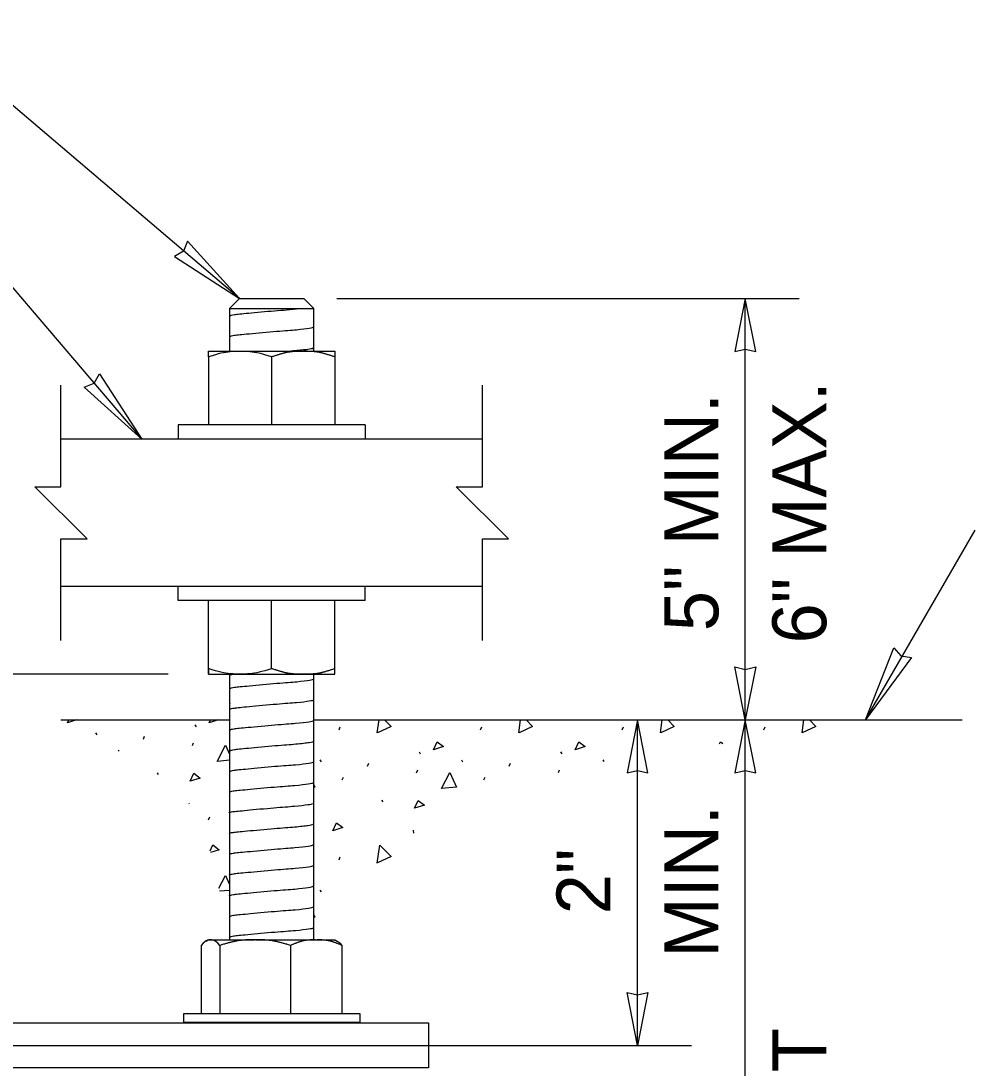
# Model space of a CAD drawing. Extents: x 99862 to 103680, y 99594 to 102199.
# Drawn here: x 101383.8 to 101666.8, y 100917.9 to 101228.5 of the extents above; entities that cross this region are included whole.
import ezdxf

# ---------------------------------------------------------------- set-up
doc = ezdxf.new("R2010")
doc.units = 0
for name, color, linetype in [('Level 15', 7, 'Continuous'), ('Level 19', 7, 'Continuous'), ('Level 2', 7, 'Continuous'), ('Level 20', 7, 'Continuous'), ('Level 9', 7, 'Continuous')]:
    doc.layers.add(name, color=color, linetype=linetype)

msp = doc.modelspace()

# ---------------------------------------------------------------- linework, layer by layer
at = {"layer": 'Level 15'}
for p, q in [((101448.66, 101146.14), (101351.93, 101228.51)), ((101370.94, 101161.59), (101419.68, 101104.48)), ((101477.49, 101146.14), (101515.57, 101146.14)), ((101515.57, 101146.14), (101614.68, 101146.14)), ((101598.68, 101021.14), (101598.68, 101146.14)), ((101634.32, 101021.14), (101666.82, 101077.43)), ((101427.43, 101034.69), (101297.26, 101034.69)), ((101435.38, 101019.67), (101435.75, 101019.11)), ((101478.16, 101018.26), (101478.54, 101019.1)), ((101520.16, 101018.26), (101520.54, 101019.1)), ((101562.16, 101018.26), (101562.54, 101019.1)), ((101566.68, 100924.6), (101566.68, 101021.14)), ((101598.68, 100723.67), (101598.68, 101021.14)), ((101604.16, 101018.26), (101604.54, 101019.1)), ((101405.93, 101017.29), (101406.31, 101016.74)), ((101420.12, 101015.47), (101420.5, 101016.31)), ((101434.67, 101013.52), (101435.04, 101014.36)), ((101412.77, 101011.84), (101412.94, 101012.22)), ((101472.46, 101009.27), (101472.83, 101008.71)), ((101501.9, 101011.65), (101502.27, 101011.09)), ((101514.46, 101009.27), (101514.83, 101008.71)), ((101543.9, 101011.65), (101544.27, 101011.09)), ((101556.46, 101009.27), (101556.75, 101008.84)), ((101486.64, 101007.45), (101487.02, 101008.29)), ((101501.19, 101005.5), (101501.57, 101006.34)), ((101528.64, 101007.45), (101529.02, 101008.29)), ((101543.23, 101005.6), (101543.57, 101006.34)), ((101424.23, 101005.41), (101424.53, 101004.96)), ((101479.09, 101003.36), (101479.47, 101004.2)), ((101521.09, 101003.36), (101521.47, 101004.2)), ((101490.75, 100997.39), (101491.12, 100996.83)), ((101433.65, 100996.47), (101433.67, 100996.29)), ((101439.47, 100991.52), (101439.84, 100992.36)), ((101500.17, 100988.45), (101500.27, 100987.61)), ((101478.16, 100979.67), (101478.54, 100980.51)), ((101472.46, 100970.68), (101472.83, 100970.13)), ((101318.38, 100924.6), (101582.68, 100924.6))]:
    msp.add_line(p, q, dxfattribs=at)
for points in [[(101448.66, 101146.14), (101433.18, 101163.18), (101432.06, 101160.22), (101429.32, 101158.63)], [(101598.68, 101146.14), (101595.6, 101130.41), (101598.68, 101131.14), (101601.77, 101130.41)], [(101419.68, 101104.48), (101402.59, 101119.91), (101405.55, 101121.04), (101407.13, 101123.78)], [(101634.32, 101021.14), (101642.75, 101042.56), (101644.85, 101040.19), (101647.98, 101039.68)], [(101598.68, 101021.14), (101595.6, 101036.86), (101598.68, 101036.14), (101601.77, 101036.86)], [(101566.68, 101021.14), (101563.6, 101005.41), (101566.68, 101006.14), (101569.77, 101005.41)], [(101598.68, 101021.14), (101595.6, 101005.41), (101598.68, 101006.14), (101601.77, 101005.41)], [(101566.68, 100924.6), (101563.6, 100940.33), (101566.68, 100939.6), (101569.77, 100940.33)]]:
    msp.add_lwpolyline(points, close=True, dxfattribs=at)
for points in [[(101395.68, 101044.73), (101395.68, 101074.86), (101403.43, 101074.86), (101387.94, 101090.35), (101395.68, 101090.35), (101395.68, 101120.48)], [(101520.68, 101044.73), (101520.68, 101074.86), (101528.43, 101074.86), (101512.94, 101090.35), (101520.68, 101090.35), (101520.68, 101120.48)], [(101397.65, 101020.32), (101398.05, 101021.14)], [(101400.28, 101021.14), (101397.65, 101020.32)], [(101439.65, 101020.32), (101440.05, 101021.14)], [(101442.28, 101021.14), (101439.65, 101020.32)], [(101489.5, 101017.3), (101490.04, 101021.14)], [(101491.69, 101021.14), (101493.58, 101019.18), (101489.59, 101017.33)], [(101531.5, 101017.3), (101532.04, 101021.14)], [(101533.69, 101021.14), (101535.58, 101019.18), (101531.59, 101017.33)], [(101573.5, 101017.3), (101574.04, 101021.14)], [(101575.69, 101021.14), (101577.58, 101019.18), (101573.59, 101017.33)], [(101615.5, 101017.3), (101616.04, 101021.14)], [(101617.69, 101021.14), (101619.58, 101019.18), (101615.59, 101017.33)], [(101441.98, 101008.86), (101444.5, 101013.62), (101445.68, 101010.97)], [(101506.17, 101012.3), (101507.29, 101014.63), (101509.16, 101013.23), (101506.17, 101012.3)], [(101548.17, 101012.3), (101549.29, 101014.63), (101551.16, 101013.23), (101548.17, 101012.3)], [(101591, 101014.02), (101591.29, 101014.63), (101591.96, 101014.13)], [(101445.68, 101009.17), (101442.08, 101008.86)], [(101434.02, 101002.99), (101435.13, 101005.32), (101437, 101003.92), (101434.02, 101002.99)], [(101508.51, 101000.84), (101511.02, 101005.59), (101512.98, 101001.21), (101508.6, 101000.84)], [(101470.68, 101001.88), (101470.98, 101001.21), (101470.68, 101001.19)], [(101500.54, 100994.97), (101501.66, 100997.3), (101503.52, 100995.9), (101500.54, 100994.97)], [(101476.32, 100988.3), (101477.43, 100990.63), (101479.3, 100989.23), (101476.32, 100988.3)], [(101439.92, 100982.29), (101440.77, 100984.06), (101442.64, 100982.66), (101440.03, 100981.85)], [(101489.5, 100978.71), (101490.24, 100984.04), (101493.58, 100980.59), (101489.59, 100978.74)], [(101442.48, 100971.21), (101444.5, 100975.03), (101445.68, 100972.38)], [(101445.68, 100970.58), (101442.67, 100970.32)], [(101470.68, 100963.29), (101470.98, 100962.63), (101470.68, 100962.6)]]:
    msp.add_lwpolyline(points, dxfattribs=at)
at = {"layer": 'Level 19'}
msp.add_lwpolyline([(101318.38, 100931.28), (101504.66, 100931.28), (101504.66, 100917.92), (101318.38, 100917.92)], dxfattribs=at)
at = {"layer": 'Level 2'}
for p, q in [((101395.68, 101021.14), (101445.68, 101021.14)), ((101470.68, 101021.14), (101662.99, 101021.14))]:
    msp.add_line(p, q, dxfattribs=at)
at = {"layer": 'Level 9'}
for p, q in [((101448.66, 101146.14), (101445.68, 101143.16)), ((101448.66, 101146.14), (101467.71, 101146.14)), ((101470.68, 101143.16), (101467.71, 101146.14)), ((101445.68, 101143.16), (101470.68, 101143.16)), ((101445.68, 101143.16), (101445.68, 101130.52)), ((101470.68, 101130.52), (101470.68, 101143.16)), ((101439.43, 101130.52), (101467.77, 101130.52)), ((101467.77, 101130.52), (101476.93, 101130.52)), ((101439.43, 101128.85), (101439.43, 101108.65)), ((101458.18, 101128.85), (101458.18, 101108.65)), ((101476.93, 101128.85), (101476.93, 101108.65)), ((101485.96, 101108.65), (101430.41, 101108.65)), ((101430.41, 101108.65), (101430.41, 101104.48)), ((101458.18, 101108.65), (101439.43, 101108.65)), ((101476.93, 101108.65), (101458.18, 101108.65)), ((101485.96, 101108.65), (101485.96, 101104.48)), ((101520.68, 101104.48), (101395.68, 101104.48)), ((101520.68, 101060.73), (101395.68, 101060.73)), ((101430.41, 101056.57), (101430.41, 101060.73)), ((101485.96, 101056.57), (101485.96, 101060.73)), ((101485.96, 101056.57), (101430.41, 101056.57)), ((101458.18, 101056.57), (101439.43, 101056.57)), ((101439.43, 101036.37), (101439.43, 101056.57)), ((101476.93, 101056.57), (101458.18, 101056.57)), ((101458.18, 101036.36), (101458.18, 101056.57)), ((101476.93, 101036.36), (101476.93, 101056.57)), ((101439.43, 101034.69), (101467.34, 101034.69)), ((101445.68, 101034.69), (101445.68, 100955.94)), ((101448.47, 101034.69), (101449.15, 101034.69)), ((101467.11, 101034.69), (101468, 101034.69)), ((101467.77, 101034.69), (101467.34, 101034.69)), ((101467.77, 101034.69), (101467.34, 101034.69)), ((101467.77, 101034.69), (101476.93, 101034.69)), ((101470.68, 100955.94), (101470.68, 101034.69)), ((101437.22, 100954.27), (101437.22, 100934.07)), ((101438.72, 100955.56), (101439.39, 100955.94)), ((101439.39, 100955.94), (101453.05, 100955.94)), ((101442.83, 100954.27), (101442.83, 100934.07)), ((101453.52, 100955.94), (101453.05, 100955.94)), ((101453.52, 100955.94), (101453.05, 100955.94)), ((101453.52, 100955.94), (101471.72, 100955.94)), ((101462.61, 100955.94), (101463.37, 100955.94)), ((101463.74, 100954.27), (101463.74, 100934.07)), ((101471.72, 100955.94), (101476.89, 100955.94)), ((101476.11, 100955.94), (101476.37, 100955.94)), ((101476.89, 100955.94), (101477.55, 100955.56)), ((101479.04, 100954.27), (101479.04, 100934.07))]:
    msp.add_line(p, q, dxfattribs=at)
msp.add_lwpolyline([(101484.33, 100931.37), (101432.13, 100931.37), (101432.13, 100934.07), (101484.33, 100934.07)], close=True, dxfattribs=at)
for points, degree in [([(101445.67, 101140.97), (101445.71, 101141), (101445.76, 101141.04), (101446.62, 101141.42), (101450.62, 101141.77), (101459.36, 101142.6), (101463.79, 101142.9), (101466.51, 101143.16)], 3), ([(101445.67, 101134.83), (101445.71, 101134.86), (101445.76, 101134.9), (101446.62, 101135.28), (101450.62, 101135.63), (101460.33, 101136.55), (101465.84, 101136.9), (101469.8, 101137.41), (101470.55, 101137.57), (101470.67, 101137.76)], 3), ([(101439.43, 101128.85), (101439.43, 101129.87), (101439.43, 101130.52), (101439.43, 101130.52)], 2), ([(101458.18, 101128.85), (101455.12, 101129.87), (101452.01, 101130.52), (101445.64, 101130.52), (101442.5, 101129.87), (101439.43, 101128.85)], 3), ([(101467.34, 101130.52), (101464.23, 101130.5), (101461.17, 101129.85), (101458.18, 101128.85)], 2), ([(101462.26, 101130.52), (101464.75, 101130.72), (101466.98, 101130.91), (101469.72, 101131.26), (101470.44, 101131.41), (101470.67, 101131.63)], 3), ([(101476.93, 101128.85), (101473.93, 101129.85), (101470.89, 101130.5), (101467.77, 101130.52)], 2), ([(101476.93, 101130.52), (101476.93, 101130.47), (101476.93, 101129.82), (101476.93, 101128.85)], 2), ([(101439.43, 101034.69), (101439.43, 101034.69), (101439.43, 101035.35), (101439.43, 101036.37)], 2), ([(101458.18, 101036.36), (101455.12, 101035.34), (101452.01, 101034.69), (101445.64, 101034.69), (101442.5, 101035.34), (101439.43, 101036.37)], 3), ([(101439.43, 101036.36), (101439.43, 101035.35), (101439.43, 101034.69), (101439.43, 101034.69)], 2), ([(101439.43, 101034.69), (101439.43, 101034.69), (101439.43, 101034.69), (101439.43, 101034.69)], 2), ([(101447.36, 101034.69), (101446.71, 101034.63), (101446.27, 101034.57), (101446.01, 101034.51), (101445.8, 101034.47), (101445.71, 101034.42), (101445.75, 101034.37)], 4), ([(101445.75, 101034.42), (101445.74, 101034.4), (101445.74, 101034.39), (101445.75, 101034.37)], 3), ([(101467.34, 101034.69), (101464.23, 101034.72), (101461.17, 101035.37), (101458.18, 101036.36)], 2), ([(101476.93, 101036.36), (101473.93, 101035.36), (101470.89, 101034.72), (101467.77, 101034.69)], 2), ([(101476.93, 101034.69), (101476.93, 101034.74), (101476.93, 101035.39), (101476.93, 101036.36)], 2), ([(101445.66, 101030.38), (101445.7, 101030.42), (101445.76, 101030.47), (101446.66, 101030.85), (101450.7, 101031.19), (101460.42, 101032.12), (101465.91, 101032.47), (101469.86, 101032.98), (101470.59, 101033.15), (101470.66, 101033.34)], 3), ([(101445.75, 101030.27), (101445.71, 101030.25), (101445.71, 101030.22), (101445.75, 101030.19)], 3), ([(101445.66, 101024.24), (101445.69, 101024.28), (101445.75, 101024.32), (101446.61, 101024.69), (101450.61, 101025.04), (101460.32, 101025.97), (101465.83, 101026.32), (101469.79, 101026.82), (101470.54, 101026.99), (101470.66, 101027.18)], 3), ([(101445.75, 101026.11), (101445.72, 101026.09), (101445.72, 101026.06), (101445.75, 101026.04)], 3), ([(101445.75, 101021.93), (101445.71, 101021.9), (101445.71, 101021.88), (101445.75, 101021.85)], 3), ([(101445.79, 101018.16), (101445.81, 101018.18), (101445.83, 101018.19), (101446.54, 101018.54), (101450.23, 101018.86), (101459.8, 101019.77), (101465.51, 101020.14), (101469.71, 101020.66), (101470.49, 101020.81), (101470.67, 101021)], 3), ([(101445.87, 101012.02), (101445.89, 101012.03), (101445.91, 101012.05), (101446.61, 101012.39), (101450.3, 101012.72), (101459.87, 101013.63), (101465.59, 101013.99), (101469.79, 101014.52), (101470.56, 101014.67), (101470.75, 101014.85)], 3), ([(101445.76, 101005.87), (101445.78, 101005.88), (101445.8, 101005.89), (101446.51, 101006.24), (101450.2, 101006.57), (101459.77, 101007.48), (101465.48, 101007.84), (101469.68, 101008.36), (101470.46, 101008.52), (101470.64, 101008.7)], 3), ([(101445.56, 100999.73), (101445.58, 100999.74), (101445.6, 100999.75), (101446.3, 101000.1), (101449.99, 101000.43), (101459.57, 101001.34), (101465.28, 101001.7), (101469.48, 101002.22), (101470.25, 101002.38), (101470.44, 101002.56)], 3), ([(101445.45, 100993.57), (101445.47, 100993.59), (101445.49, 100993.6), (101446.2, 100993.95), (101449.89, 100994.27), (101459.46, 100995.19), (101465.17, 100995.55), (101469.37, 100996.07), (101470.15, 100996.23), (101470.33, 100996.41)], 3), ([(101445.53, 100987.43), (101445.55, 100987.44), (101445.57, 100987.46), (101446.28, 100987.8), (101449.97, 100988.13), (101459.54, 100989.04), (101465.25, 100989.4), (101469.45, 100989.93), (101470.23, 100990.08), (101470.41, 100990.26)], 3), ([(101445.61, 100981.29), (101445.62, 100981.3), (101445.65, 100981.31), (101446.35, 100981.66), (101450.04, 100981.99), (101459.61, 100982.9), (101465.33, 100983.26), (101469.53, 100983.78), (101470.3, 100983.94), (101470.49, 100984.12)], 3), ([(101445.68, 100975.15), (101445.7, 100975.16), (101445.72, 100975.17), (101446.43, 100975.52), (101450.12, 100975.85), (101459.69, 100976.76), (101465.41, 100977.12), (101469.6, 100977.64), (101470.38, 100977.8), (101470.57, 100977.98)], 3), ([(101445.58, 100968.99), (101445.6, 100969.01), (101445.62, 100969.02), (101446.32, 100969.37), (101450.01, 100969.69), (101459.59, 100970.61), (101465.3, 100970.97), (101469.5, 100971.49), (101470.27, 100971.65), (101470.46, 100971.83)], 3), ([(101445.66, 100962.85), (101445.67, 100962.86), (101445.69, 100962.88), (101446.4, 100963.22), (101450.09, 100963.55), (101459.66, 100964.46), (101465.38, 100964.82), (101469.57, 100965.35), (101470.35, 100965.5), (101470.54, 100965.68)], 3), ([(101445.73, 100956.71), (101445.75, 100956.72), (101445.77, 100956.73), (101446.48, 100957.08), (101450.17, 100957.41), (101459.74, 100958.32), (101465.46, 100958.68), (101469.65, 100959.2), (101470.43, 100959.36), (101470.62, 100959.54)], 3), ([(101442.83, 100954.27), (101441.91, 100955.29), (101440.98, 100955.94), (101439.08, 100955.95), (101438.14, 100955.29), (101437.22, 100954.27)], 3), ([(101453.05, 100955.94), (101449.57, 100955.92), (101446.16, 100955.27), (101442.83, 100954.27)], 2), ([(101463.74, 100954.27), (101460.39, 100955.27), (101457, 100955.92), (101453.52, 100955.94)], 2), ([(101471.06, 100955.94), (101468.58, 100955.89), (101466.11, 100955.24), (101463.74, 100954.27)], 2), ([(101479.04, 100954.27), (101476.66, 100955.25), (101474.19, 100955.89), (101471.72, 100955.94)], 2), ([(101476.37, 100955.94), (101476.76, 100955.92), (101477.14, 100955.79), (101477.51, 100955.58)], 2), ([(101477.51, 100955.58), (101478.03, 100955.29), (101478.54, 100954.84), (101479.04, 100954.27)], 2)]:
    msp.add_open_spline(points, degree=degree, dxfattribs=at)

# ---------------------------------------------------------------- texts
at = {"layer": 'Level 20'}
for s, p in [('6" MAX.', (101622.68, 101043.86)), ('5" MIN.', (101590.68, 101047.49)), ('MIN.', (101590.68, 100950.69)), ('2"', (101558.68, 100963.51)), ('EMBEDMENT', (101622.68, 100793.01))]:
    msp.add_text(s, height=16, rotation=90, dxfattribs=at).set_placement(p)

doc.saveas('drawing.dxf')
